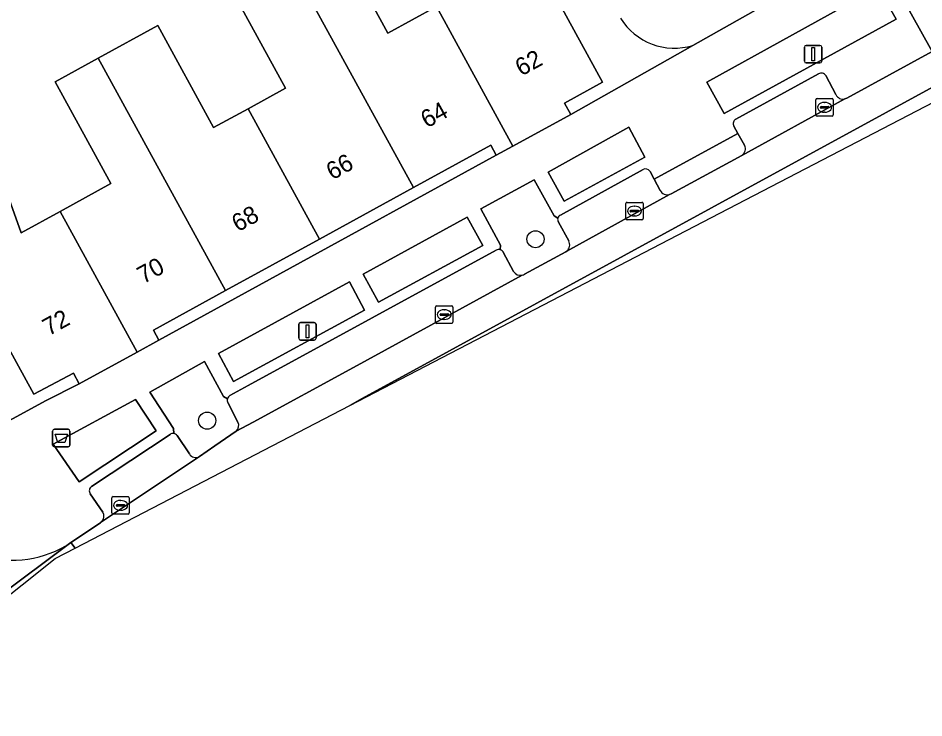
# Model space of a CAD drawing. Extents: x 159262 to 160143, y 383399 to 384319.
# Drawn here: x 159940.2 to 159992.1, y 383693.1 to 383733.1 of the extents above; entities that cross this region are included whole.
import ezdxf

# ---------------------------------------------------------------- set-up
doc = ezdxf.new("R2010")
doc.units = 0
for name, color, linetype in [('IMGEO_Afvalbak', 7, 'Continuous'), ('IMGEO_Boom', 7, 'Continuous'), ('IMGEO_Erf', 7, 'Continuous'), ('IMGEO_Groenvoorziening', 7, 'Continuous'), ('IMGEO_Kolk', 7, 'Continuous'), ('IMGEO_Lichtmast', 7, 'Continuous'), ('IMGEO_Pand', 7, 'Continuous'), ('IMGEO_Pand_nummerreeks', 7, 'Continuous'), ('IMGEO_Parkeervlak_open', 7, 'Continuous'), ('IMGEO_Rijbaan_lokaal_gesloten', 7, 'Continuous'), ('IMGEO_Rijbaan_lokaal_open', 7, 'Continuous'), ('IMGEO_Voetpad_open', 7, 'Continuous')]:
    doc.layers.add(name, color=color, linetype=linetype)

msp = doc.modelspace()

# ---------------------------------------------------------------- linework, layer by layer
at = {"layer": 'IMGEO_Afvalbak'}
for p, q in [((159942.167, 383708.669), (159942.167, 383709.469)), ((159942.167, 383709.469), (159942.167, 383708.669)), ((159942.267, 383709.569), (159943.057, 383709.569)), ((159943.057, 383709.569), (159942.267, 383709.569)), ((159943.157, 383709.469), (159943.157, 383708.669)), ((159943.157, 383708.669), (159943.157, 383709.469)), ((159943.057, 383708.569), (159942.267, 383708.569)), ((159942.267, 383708.569), (159943.057, 383708.569))]:
    msp.add_line(p, q, dxfattribs=at)
msp.add_lwpolyline([(159942.31, 383709.283), (159943.014, 383709.283), (159942.865, 383708.813), (159942.459, 383708.813), (159942.31, 383709.283)], dxfattribs=at)
for centre, start, end in [((159942.267, 383709.469), 90, 180), ((159942.267, 383709.469), 90, 180), ((159943.057, 383709.469), 0, 90), ((159943.057, 383709.469), 360, 90), ((159942.267, 383708.669), 180, 270), ((159942.267, 383708.669), 180, 270), ((159943.057, 383708.669), 270, 0), ((159943.057, 383708.669), 270, 0)]:
    msp.add_arc(centre, 0.1, start, end, dxfattribs=at)
at = {"layer": 'IMGEO_Boom'}
for centre in [(159969.814, 383720.445), (159951.016, 383710.064)]:
    msp.add_circle(centre, 0.489, dxfattribs=at)
at = {"layer": 'IMGEO_Erf'}
for points in [[(159958.089, 383738.223), (159961.365, 383732.243), (159964.141, 383733.764)], [(159938.213, 383726.796), (159940.371, 383720.813), (159942.591, 383722.03), (159945.505, 383723.627), (159942.313, 383729.453), (159944.778, 383730.804), (159948.187, 383732.671), (159951.385, 383726.834), (159953.356, 383727.914), (159955.5, 383729.088), (159952.249, 383735.023)], [(159971.246, 383733.809), (159973.648, 383729.424), (159971.474, 383728.233), (159971.829, 383727.583), (159978.831, 383731.538)], [(159937.58, 383708.929), (159941.752, 383711.19), (159943.691, 383712.172), (159943.353, 383712.789), (159941.081, 383711.575), (159937.658, 383717.819)]]:
    msp.add_lwpolyline(points, dxfattribs=at)
msp.add_arc((159977.766, 383735.025), 3.646, 211.9652, 286.9771, dxfattribs=at)
at = {"layer": 'IMGEO_Groenvoorziening'}
for points in [[(159978.831, 383731.538), (159994.527, 383740.405)], [(159994.537, 383734.441), (159994.294, 383734.586), (159993.008, 383736.914), (159990.213, 383735.347), (159992.522, 383731.189), (159994.969, 383732.53)], [(159971.087, 383721.647), (159970.885, 383721.778), (159969.746, 383723.845), (159966.681, 383722.193), (159967.801, 383720.105), (159967.799, 383719.841)], [(159971.716, 383720.345), (159971.13, 383721.424)], [(159967.972, 383719.7), (159968.555, 383718.607)], [(159969.184, 383718.442), (159971.544, 383719.727), (159971.605, 383719.768)], [(159952.174, 383711.308), (159951.944, 383711.443), (159950.87, 383713.456), (159947.738, 383711.691), (159949.088, 383709.613), (159949.104, 383709.324)], [(159952.778, 383709.98), (159952.191, 383711.093)], [(159949.29, 383709.21), (159949.998, 383708.159)], [(159950.567, 383708.004), (159951.462, 383708.619), (159952.673, 383709.466)]]:
    msp.add_lwpolyline(points, dxfattribs=at)
for points in [[(159989.431, 383734.872), (159979.627, 383729.424), (159980.616, 383727.637), (159990.465, 383733.029)], [(159975.154, 383726.861), (159970.532, 383724.29), (159971.457, 383722.613), (159976.083, 383725.141)], [(159965.897, 383721.708), (159959.948, 383718.445), (159960.825, 383716.845), (159966.803, 383720.083)], [(159960.029, 383716.394), (159959.157, 383718.002), (159951.665, 383713.906), (159952.523, 383712.297)], [(159948.089, 383709.485), (159946.915, 383711.279), (159942.194, 383708.722), (159943.683, 383706.558)]]:
    msp.add_lwpolyline(points, close=True, dxfattribs=at)
for centre, radius, start, end in [((159977.766, 383735.025), 3.646, 211.9652, 286.9771), ((159971.35, 383721.582), 0.271, 166.1695, 215.6588), ((159971.324, 383720.121), 0.452, 308.5215, 29.7001), ((159967.708, 383719.552), 0.303, 29.1874, 72.4506), ((159968.949, 383718.83), 0.453, 209.4968, 282.5998), ((159968.961, 383718.806), 0.427, 281.7902, 301.5218), ((159952.486, 383711.224), 0.323, 164.9888, 204.0531), ((159952.399, 383709.79), 0.424, 310.2833, 26.6256), ((159949.055, 383709.036), 0.293, 36.6047, 80.3868), ((159950.367, 383708.392), 0.436, 212.2591, 297.2647)]:
    msp.add_arc(centre, radius, start, end, dxfattribs=at)
at = {"layer": 'IMGEO_Kolk'}
for p, q in [((159985.866, 383727.565), (159985.866, 383728.417)), ((159985.941, 383728.491), (159986.793, 383728.491)), ((159986.867, 383728.417), (159986.867, 383727.565)), ((159986.125, 383727.985), (159986.125, 383727.997)), ((159986.563, 383727.948), (159986.165, 383727.948)), ((159986.168, 383728.034), (159986.566, 383728.034)), ((159986.354, 383728.271), (159986.379, 383728.271)), ((159986.609, 383727.997), (159986.609, 383727.985)), ((159986.793, 383727.491), (159985.941, 383727.491)), ((159986.377, 383727.711), (159986.352, 383727.711)), ((159974.979, 383721.629), (159974.979, 383722.481)), ((159975.054, 383722.555), (159975.906, 383722.555)), ((159975.281, 383722.098), (159975.679, 383722.098)), ((159975.467, 383722.335), (159975.492, 383722.335)), ((159975.98, 383722.481), (159975.98, 383721.629)), ((159975.238, 383722.049), (159975.238, 383722.061)), ((159975.676, 383722.012), (159975.278, 383722.012)), ((159975.49, 383721.775), (159975.465, 383721.775)), ((159975.722, 383722.061), (159975.722, 383722.049)), ((159975.906, 383721.555), (159975.054, 383721.555)), ((159964.088, 383715.706), (159964.088, 383716.558)), ((159964.163, 383716.632), (159965.015, 383716.632)), ((159964.576, 383716.412), (159964.601, 383716.412)), ((159965.089, 383716.558), (159965.089, 383715.706)), ((159964.347, 383716.126), (159964.347, 383716.138)), ((159964.785, 383716.089), (159964.387, 383716.089)), ((159964.39, 383716.175), (159964.788, 383716.175)), ((159964.599, 383715.852), (159964.574, 383715.852)), ((159964.831, 383716.138), (159964.831, 383716.126)), ((159965.015, 383715.632), (159964.163, 383715.632)), ((159945.556, 383704.79), (159945.556, 383705.642)), ((159945.631, 383705.716), (159946.483, 383705.716)), ((159946.044, 383705.496), (159946.069, 383705.496)), ((159946.557, 383705.642), (159946.557, 383704.79)), ((159945.815, 383705.21), (159945.815, 383705.222)), ((159946.253, 383705.173), (159945.855, 383705.173)), ((159945.858, 383705.259), (159946.256, 383705.259)), ((159946.299, 383705.222), (159946.299, 383705.21)), ((159946.483, 383704.716), (159945.631, 383704.716)), ((159946.067, 383704.936), (159946.042, 383704.936))]:
    msp.add_line(p, q, dxfattribs=at)
for points in [[(159985.866, 383727.565), (159985.866, 383728.417)], [(159985.941, 383728.491), (159986.793, 383728.491)], [(159986.867, 383728.417), (159986.867, 383727.565)], [(159986.793, 383727.491), (159985.941, 383727.491)], [(159974.979, 383721.629), (159974.979, 383722.481)], [(159975.054, 383722.555), (159975.906, 383722.555)], [(159975.98, 383722.481), (159975.98, 383721.629)], [(159975.906, 383721.555), (159975.054, 383721.555)], [(159964.088, 383715.706), (159964.088, 383716.558)], [(159964.163, 383716.632), (159965.015, 383716.632)], [(159965.089, 383716.558), (159965.089, 383715.706)], [(159965.015, 383715.632), (159964.163, 383715.632)], [(159945.556, 383704.79), (159945.556, 383705.642)], [(159945.631, 383705.716), (159946.483, 383705.716)], [(159946.557, 383705.642), (159946.557, 383704.79)], [(159946.483, 383704.716), (159945.631, 383704.716)]]:
    msp.add_lwpolyline(points, dxfattribs=at)
for centre, radius, start, end in [((159985.943, 383728.415), 0.0765, 91.552, 178.448), ((159985.943, 383728.415), 0.0765, 91.552, 178.448), ((159986.791, 383728.415), 0.0765, 1.552, 88.448), ((159986.791, 383728.415), 0.0765, 1.552, 88.448), ((159986.165, 383727.994), 0.0403, 85.8775, 175.7526), ((159986.162, 383727.984), 0.0366, 178.938, 274.7102), ((159986.566, 383727.991), 0.043, 264.8664, 352.4533), ((159986.57, 383727.996), 0.0386, 1.7309, 96.639), ((159985.943, 383727.567), 0.0765, 181.552, 268.448), ((159985.943, 383727.567), 0.0765, 181.552, 268.448), ((159986.791, 383727.567), 0.0765, 271.552, 358.448), ((159986.791, 383727.567), 0.0765, 271.552, 358.448), ((159975.056, 383722.479), 0.0765, 91.552, 178.448), ((159975.056, 383722.479), 0.0765, 91.552, 178.448), ((159975.278, 383722.058), 0.0403, 85.8775, 175.7526), ((159975.683, 383722.06), 0.0386, 1.7309, 96.639), ((159975.904, 383722.479), 0.0765, 1.552, 88.448), ((159975.904, 383722.479), 0.0765, 1.552, 88.448), ((159975.056, 383721.631), 0.0765, 181.552, 268.448), ((159975.056, 383721.631), 0.0765, 181.552, 268.448), ((159975.275, 383722.048), 0.0366, 178.938, 274.7102), ((159975.679, 383722.055), 0.043, 264.8664, 352.4533), ((159975.904, 383721.631), 0.0765, 271.552, 358.448), ((159975.904, 383721.631), 0.0765, 271.552, 358.448), ((159964.165, 383716.556), 0.0765, 91.552, 178.448), ((159964.165, 383716.556), 0.0765, 91.552, 178.448), ((159965.013, 383716.556), 0.0765, 1.552, 88.448), ((159965.013, 383716.556), 0.0765, 1.552, 88.448), ((159964.387, 383716.135), 0.0403, 85.8775, 175.7526), ((159964.384, 383716.125), 0.0366, 178.938, 274.7102), ((159964.788, 383716.132), 0.043, 264.8664, 352.4533), ((159964.792, 383716.137), 0.0386, 1.7309, 96.639), ((159964.165, 383715.708), 0.0765, 181.552, 268.448), ((159964.165, 383715.708), 0.0765, 181.552, 268.448), ((159965.013, 383715.708), 0.0765, 271.552, 358.448), ((159965.013, 383715.708), 0.0765, 271.552, 358.448), ((159945.633, 383705.64), 0.0765, 91.552, 178.448), ((159945.633, 383705.64), 0.0765, 91.552, 178.448), ((159946.481, 383705.64), 0.0765, 1.552, 88.448), ((159946.481, 383705.64), 0.0765, 1.552, 88.448), ((159945.855, 383705.219), 0.0403, 85.8775, 175.7526), ((159945.852, 383705.209), 0.0366, 178.938, 274.7102), ((159946.256, 383705.216), 0.043, 264.8664, 352.4533), ((159946.26, 383705.221), 0.0386, 1.7309, 96.639), ((159945.633, 383704.792), 0.0765, 181.552, 268.448), ((159945.633, 383704.792), 0.0765, 181.552, 268.448), ((159946.481, 383704.792), 0.0765, 271.552, 358.448), ((159946.481, 383704.792), 0.0765, 271.552, 358.448)]:
    msp.add_arc(centre, radius, start, end, dxfattribs=at)
for centre, major_axis, ratio, start_param, end_param in [((159986.353, 383727.991), (-0.387, 0.002), 0.722429, 4.712389, 7.853982), ((159986.378, 383727.991), (-0.39, 0.002), 0.717154, 1.570796, 4.712389), ((159975.466, 383722.055), (-0.387, 0.002), 0.722429, 4.712389, 7.853982), ((159975.491, 383722.055), (-0.39, 0.002), 0.717154, 1.570796, 4.712389), ((159964.575, 383716.132), (-0.387, 0.002), 0.722429, 4.712389, 7.853982), ((159964.6, 383716.132), (-0.39, 0.002), 0.717154, 1.570796, 4.712389), ((159946.043, 383705.216), (-0.387, 0.002), 0.722429, 4.712389, 7.853982), ((159946.068, 383705.216), (-0.39, 0.002), 0.717154, 1.570796, 4.712389)]:
    msp.add_ellipse(centre, major_axis=major_axis, ratio=ratio, start_param=start_param, end_param=end_param, dxfattribs=at)
at = {"layer": 'IMGEO_Lichtmast'}
for p, q in [((159985.212, 383730.633), (159985.212, 383731.433)), ((159985.212, 383731.433), (159985.212, 383730.633)), ((159985.312, 383731.533), (159986.102, 383731.533)), ((159986.102, 383731.533), (159985.312, 383731.533)), ((159986.202, 383731.433), (159986.202, 383730.633)), ((159986.202, 383730.633), (159986.202, 383731.433)), ((159986.102, 383730.533), (159985.312, 383730.533)), ((159985.312, 383730.533), (159986.102, 383730.533)), ((159956.259, 383714.778), (159956.259, 383715.578)), ((159956.259, 383715.578), (159956.259, 383714.778)), ((159956.359, 383715.678), (159957.149, 383715.678)), ((159957.149, 383715.678), (159956.359, 383715.678)), ((159957.249, 383715.578), (159957.249, 383714.778)), ((159957.249, 383714.778), (159957.249, 383715.578)), ((159957.149, 383714.678), (159956.359, 383714.678)), ((159956.359, 383714.678), (159957.149, 383714.678))]:
    msp.add_line(p, q, dxfattribs=at)
for points in [[(159985.632, 383731.408), (159985.782, 383731.408), (159985.782, 383730.658), (159985.632, 383730.658), (159985.632, 383731.408)], [(159956.679, 383715.553), (159956.829, 383715.553), (159956.829, 383714.803), (159956.679, 383714.803), (159956.679, 383715.553)]]:
    msp.add_lwpolyline(points, dxfattribs=at)
for centre, start, end in [((159985.312, 383731.433), 90, 180), ((159985.312, 383731.433), 90, 180), ((159986.102, 383731.433), 0, 90), ((159986.102, 383731.433), 360, 90), ((159985.312, 383730.633), 180, 270), ((159985.312, 383730.633), 180, 270), ((159986.102, 383730.633), 270, 0), ((159986.102, 383730.633), 270, 0), ((159956.359, 383715.578), 90, 180), ((159956.359, 383715.578), 90, 180), ((159957.149, 383715.578), 0, 90), ((159957.149, 383715.578), 360, 90), ((159956.359, 383714.778), 180, 270), ((159956.359, 383714.778), 180, 270), ((159957.149, 383714.778), 270, 0), ((159957.149, 383714.778), 270, 0)]:
    msp.add_arc(centre, 0.1, start, end, dxfattribs=at)
at = {"layer": 'IMGEO_Pand'}
for points in [[(159964.141, 383733.764), (159968.521, 383725.771), (159971.829, 383727.583), (159971.474, 383728.233), (159973.648, 383729.424), (159971.246, 383733.809), (159966.779, 383741.965), (159963.66, 383740.257), (159965.556, 383736.795), (159967.518, 383737.869), (159968.468, 383736.135)], [(159964.141, 383733.764), (159961.365, 383732.243), (159958.089, 383738.223), (159955.484, 383736.796), (159962.824, 383723.399), (159967.254, 383725.826), (159967.57, 383725.25), (159968.521, 383725.771)], [(159955.484, 383736.796), (159952.249, 383735.023), (159955.5, 383729.088), (159953.356, 383727.914), (159957.444, 383720.452), (159962.824, 383723.399)], [(159952.064, 383717.504), (159957.444, 383720.452), (159953.356, 383727.914), (159951.385, 383726.834), (159948.187, 383732.671), (159944.778, 383730.804)], [(159946.999, 383713.984), (159948.249, 383714.669), (159947.935, 383715.242), (159952.064, 383717.504), (159944.778, 383730.804), (159942.313, 383729.453), (159945.505, 383723.627), (159942.591, 383722.03)], [(159942.591, 383722.03), (159940.371, 383720.813), (159938.213, 383726.796), (159934.819, 383725.571), (159935.143, 383724.691), (159936.536, 383720.904), (159936.739, 383720.979), (159937.845, 383717.926), (159937.658, 383717.819), (159941.081, 383711.575), (159943.353, 383712.789), (159943.691, 383712.172), (159946.999, 383713.984)]]:
    msp.add_lwpolyline(points, close=True, dxfattribs=at)
at = {"layer": 'IMGEO_Parkeervlak_open'}
for points in [[(159986.021, 383729.9), (159981.289, 383727.319)], [(159987.014, 383728.728), (159986.434, 383729.809)], [(159981.62, 383725.234), (159987.522, 383728.468)], [(159981.173, 383726.91), (159981.408, 383726.493), (159981.788, 383725.82)], [(159975.971, 383724.435), (159971.24, 383721.829)], [(159976.958, 383723.223), (159976.613, 383723.876), (159976.374, 383724.328)], [(159971.605, 383719.768), (159977.48, 383723)], [(159971.13, 383721.424), (159971.716, 383720.345)], [(159967.568, 383719.821), (159953.361, 383712.072), (159952.317, 383711.501)], [(159968.555, 383718.607), (159967.972, 383719.7)], [(159959.388, 383713.109), (159969.048, 383718.388)], [(159952.673, 383709.466), (159953.654, 383709.972), (159959.388, 383713.109)], [(159952.191, 383711.093), (159952.778, 383709.98)], [(159948.888, 383709.276), (159944.391, 383706.301)], [(159949.998, 383708.159), (159949.29, 383709.21)], [(159944.998, 383704.306), (159944.904, 383704.223), (159944.913, 383704.229), (159950.567, 383708.004)], [(159944.322, 383705.883), (159945.039, 383704.835)]]:
    msp.add_lwpolyline(points, dxfattribs=at)
for centre, radius, start, end in [((159986.186, 383729.667), 0.285, 29.7755, 125.3726), ((159987.423, 383728.901), 0.444, 202.9347, 282.8576), ((159981.428, 383727.059), 0.295, 118.1536, 210.1778), ((159981.373, 383725.622), 0.46, 302.5176, 25.4883), ((159976.107, 383724.136), 0.329, 35.7568, 114.5043), ((159977.363, 383723.449), 0.464, 209.1259, 284.6094), ((159971.35, 383721.582), 0.271, 166.1695, 215.6588), ((159971.346, 383721.585), 0.266, 113.4049, 166.4903), ((159971.324, 383720.121), 0.452, 308.5215, 29.7001), ((159967.708, 383719.552), 0.303, 72.4638, 117.4329), ((159967.708, 383719.552), 0.303, 29.1874, 72.4506), ((159968.949, 383718.83), 0.453, 209.4968, 282.5998), ((159952.486, 383711.224), 0.323, 164.9888, 204.0531), ((159952.489, 383711.224), 0.326, 121.8726, 165.0555), ((159952.399, 383709.79), 0.424, 310.2833, 26.6256), ((159949.055, 383709.034), 0.294, 80.4494, 124.6082), ((159949.055, 383709.036), 0.293, 36.6047, 80.3868), ((159950.367, 383708.392), 0.436, 212.2591, 297.2647), ((159944.563, 383706.058), 0.298, 125.3155, 215.9377), ((159944.658, 383704.598), 0.449, 319.3183, 31.818)]:
    msp.add_arc(centre, radius, start, end, dxfattribs=at)
at = {"layer": 'IMGEO_Rijbaan_lokaal_gesloten'}
for points in [[(159994.969, 383732.53), (159992.522, 383731.189), (159987.648, 383728.517), (159987.522, 383728.468), (159981.62, 383725.234), (159977.574, 383723.036), (159977.48, 383723), (159971.605, 383719.768), (159971.544, 383719.727), (159969.184, 383718.442)], [(159943.448, 383702.759), (159959.178, 383710.934), (159959.887, 383711.324), (159994.895, 383730.432), (159996.689, 383731.42)], [(159969.048, 383718.388), (159959.388, 383713.109), (159953.654, 383709.972), (159952.673, 383709.466), (159951.462, 383708.619), (159950.567, 383708.004), (159944.913, 383704.229), (159944.904, 383704.223), (159943.207, 383703.085), (159943.448, 383702.759)]]:
    msp.add_lwpolyline(points, dxfattribs=at)
msp.add_arc((159968.961, 383718.806), 0.427, 281.7902, 301.5218, dxfattribs=at)
at = {"layer": 'IMGEO_Rijbaan_lokaal_open'}
for points in [[(159959.178, 383710.934), (159980.365, 383721.945), (160013.245, 383739.032), (160025.843, 383745.579), (160034.25, 383749.262), (160033.485, 383751.472), (160033.095, 383751.33), (160033.722, 383749.561), (160032.373, 383749.073)], [(159996.689, 383731.42), (159994.895, 383730.432), (159959.887, 383711.324), (159959.178, 383710.934)], [(159930.854, 383693.058), (159942.32, 383702.173), (159943.448, 383702.759), (159943.207, 383703.085), (159930.572, 383693.65), (159930.446, 383693.544), (159930.854, 383693.058)], [(159930.572, 383693.65), (159943.207, 383703.085)]]:
    msp.add_lwpolyline(points, dxfattribs=at)
msp.add_arc((159939.902, 383708.034), 5.951, 252.5372, 303.7387, dxfattribs=at)
at = {"layer": 'IMGEO_Voetpad_open'}
for points in [[(160028.249, 383759.288), (160011.487, 383750), (159994.527, 383740.405), (159978.831, 383731.538), (159971.829, 383727.583), (159968.521, 383725.771), (159967.57, 383725.25), (159955.18, 383718.465), (159948.249, 383714.669), (159946.999, 383713.984), (159943.691, 383712.172), (159941.752, 383711.19), (159937.58, 383708.929), (159935.975, 383707.683), (159934.209, 383706.21), (159934.314, 383705.938), (159934.625, 383705.198)], [(159987.522, 383728.468), (159987.648, 383728.517), (159992.522, 383731.189), (159990.213, 383735.347), (159993.008, 383736.914), (159994.294, 383734.586), (159994.537, 383734.441)], [(159981.289, 383727.319), (159986.021, 383729.9)], [(159986.434, 383729.809), (159987.014, 383728.728)], [(159976.374, 383724.328), (159976.613, 383723.876), (159981.408, 383726.493), (159981.173, 383726.91)], [(159981.788, 383725.82), (159981.408, 383726.493), (159976.613, 383723.876), (159976.958, 383723.223)], [(159977.48, 383723), (159977.574, 383723.036), (159981.62, 383725.234)], [(159971.24, 383721.829), (159975.971, 383724.435)], [(159967.799, 383719.841), (159967.801, 383720.105), (159966.681, 383722.193), (159969.746, 383723.845), (159970.885, 383721.778), (159971.087, 383721.647)], [(159952.317, 383711.501), (159953.361, 383712.072), (159967.568, 383719.821)], [(159949.104, 383709.324), (159949.088, 383709.613), (159947.738, 383711.691), (159950.87, 383713.456), (159951.944, 383711.443), (159952.174, 383711.308)], [(159944.391, 383706.301), (159948.888, 383709.276)], [(159945.039, 383704.835), (159944.322, 383705.883)], [(159943.207, 383703.085), (159944.904, 383704.223), (159944.998, 383704.306)]]:
    msp.add_lwpolyline(points, dxfattribs=at)
for points in [[(159990.465, 383733.029), (159980.616, 383727.637), (159979.627, 383729.424), (159989.431, 383734.872)], [(159976.083, 383725.141), (159971.457, 383722.613), (159970.532, 383724.29), (159975.154, 383726.861)], [(159967.57, 383725.25), (159967.254, 383725.826), (159962.824, 383723.399), (159957.444, 383720.452), (159952.064, 383717.504), (159947.935, 383715.242), (159948.249, 383714.669), (159955.18, 383718.465)], [(159960.825, 383716.845), (159959.948, 383718.445), (159965.897, 383721.708), (159966.803, 383720.083)], [(159960.029, 383716.394), (159952.523, 383712.297), (159951.665, 383713.906), (159959.157, 383718.002)], [(159948.089, 383709.485), (159943.683, 383706.558), (159942.194, 383708.722), (159946.915, 383711.279)]]:
    msp.add_lwpolyline(points, close=True, dxfattribs=at)
for centre, radius, start, end in [((159986.186, 383729.667), 0.285, 29.7755, 125.3726), ((159987.423, 383728.901), 0.444, 202.9347, 282.8576), ((159981.428, 383727.059), 0.295, 118.1536, 210.1778), ((159981.373, 383725.622), 0.46, 302.5176, 25.4883), ((159976.107, 383724.136), 0.329, 35.7568, 114.5043), ((159977.363, 383723.449), 0.464, 209.1259, 284.6094), ((159971.346, 383721.585), 0.266, 113.4049, 166.4903), ((159967.708, 383719.552), 0.303, 72.4638, 117.4329), ((159952.489, 383711.224), 0.326, 121.8726, 165.0555), ((159949.055, 383709.034), 0.294, 80.4494, 124.6082), ((159944.563, 383706.058), 0.298, 125.3155, 215.9377), ((159944.658, 383704.598), 0.449, 319.3183, 31.818), ((159939.902, 383708.034), 5.951, 252.5372, 303.7387)]:
    msp.add_arc(centre, radius, start, end, dxfattribs=at)

# ---------------------------------------------------------------- texts
at = {"layer": 'IMGEO_Pand_nummerreeks'}
for s, rotation, p in [('62', 28.7684, (159969.002, 383729.748)), ('64', 28.7684, (159963.593, 383726.778)), ('66', 28.7684, (159958.18, 383723.806)), ('68', 28.7684, (159952.77, 383720.836)), ('70', 28.7684, (159947.357, 383717.865)), ('72', 28.7682, (159941.94, 383714.89))]:
    msp.add_text(s, height=1, rotation=rotation, dxfattribs=at).set_placement(p)

doc.saveas('drawing.dxf')
